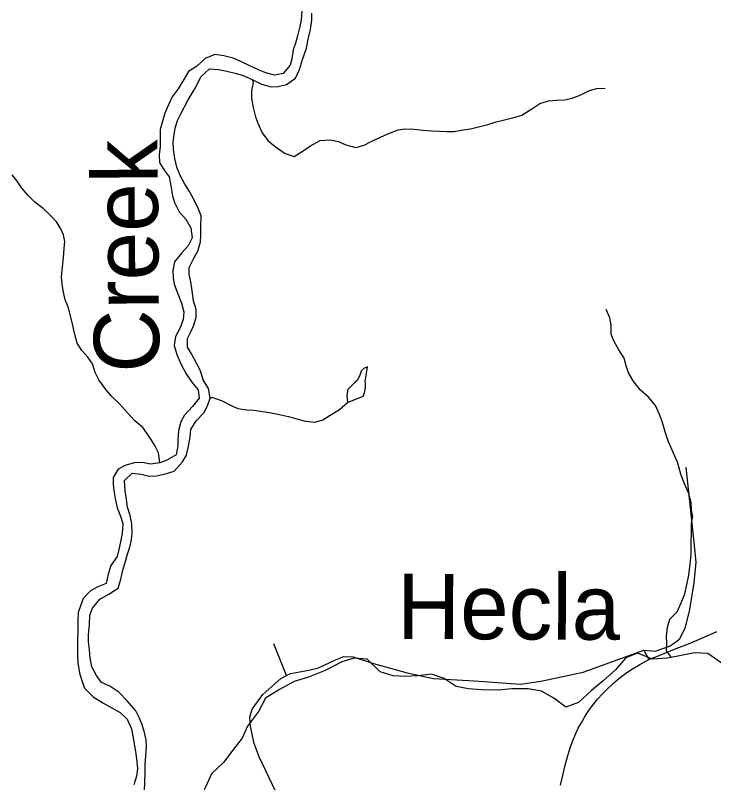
# Model space of a CAD drawing. Extents: x 0 to 34, y 0 to 22.
# Drawn here: x 3.746 to 4.76, y 17.398 to 18.512 of the extents above; entities that cross this region are included whole.
import ezdxf

# ---------------------------------------------------------------- set-up
doc = ezdxf.new("R2010")
doc.units = 0
for name, color, linetype in [('GM_X_County_Road', 7, 'Continuous'), ('GM_X_Major_River', 7, 'Continuous'), ('GM_X_Minor_Lake', 7, 'Continuous'), ('GM_X_Minor_River', 7, 'Continuous'), ('GM_X_Minor_River_Text', 7, 'Continuous'), ('GM_X_State_Route', 7, 'Continuous'), ('GM_X_Township_Road', 7, 'Continuous')]:
    doc.layers.add(name, color=color, linetype=linetype)

msp = doc.modelspace()

# ---------------------------------------------------------------- linework, layer by layer
at = {"layer": 'GM_X_County_Road'}
msp.add_lwpolyline([(4.1244, 17.385), (4.1095, 17.4154), (4.1001, 17.4361), (4.093, 17.4552), (4.0874, 17.48), (4.0866, 17.4937), (4.0899, 17.5051), (4.1055, 17.5264), (4.1314, 17.5498), (4.1395, 17.554), (4.1456, 17.5571), (4.1722, 17.5618), (4.1859, 17.565), (4.2108, 17.5766), (4.2227, 17.5817), (4.2363, 17.581), (4.266, 17.5716), (4.3146, 17.5577), (4.3531, 17.5497), (4.4121, 17.5461), (4.4791, 17.5413), (4.5087, 17.5456), (4.57, 17.5588), (4.6581, 17.5909), (4.6656, 17.5771)], dxfattribs=at)
at = {"layer": 'GM_X_Major_River'}
for points in [[(4.1618, 18.5181), (4.1611, 18.5056), (4.1592, 18.4957), (4.1558, 18.4821), (4.1527, 18.4718), (4.1493, 18.462), (4.1474, 18.449), (4.1448, 18.4396), (4.135, 18.4278), (4.1225, 18.4251), (4.1096, 18.4285), (4.0998, 18.4323), (4.0873, 18.438), (4.0745, 18.4445), (4.0624, 18.4498), (4.0488, 18.4532), (4.0356, 18.4551), (4.0219, 18.4493), (4.0095, 18.438), (3.9974, 18.4307), (3.9906, 18.419), (3.9826, 18.4053), (3.9739, 18.3935), (3.9686, 18.3821), (3.9633, 18.37), (3.9599, 18.3586), (3.9562, 18.3461), (3.9565, 18.3324), (3.9565, 18.3218), (3.955, 18.3096), (3.9554, 18.2982), (3.9622, 18.2872), (3.9694, 18.2774), (3.972, 18.2645), (3.9743, 18.25), (3.9773, 18.2402), (3.9841, 18.2269), (3.9936, 18.2163), (4.0007, 18.2034), (4.003, 18.1893), (3.9969, 18.1775), (3.9871, 18.1669), (3.9773, 18.1544), (3.9746, 18.1415), (3.9754, 18.1312), (3.9769, 18.1217), (3.9822, 18.1077), (3.9871, 18.0944), (3.9909, 18.0819), (3.9897, 18.0705), (3.9852, 18.0587), (3.9784, 18.0458), (3.9765, 18.0329), (3.9807, 18.0196), (3.9867, 18.0052), (3.9939, 17.9919), (4.0022, 17.9798), (4.0113, 17.9684), (4.0128, 17.9562), (4.0033, 17.9441), (3.9916, 17.9319), (3.9863, 17.922), (3.9829, 17.9091), (3.9818, 17.8966), (3.9818, 17.8871), (3.9795, 17.8742), (3.9659, 17.8666), (3.9561, 17.8624), (3.9425, 17.8605), (3.9307, 17.8632), (3.9186, 17.8628), (3.9054, 17.8586), (3.8956, 17.8533), (3.8884, 17.8415), (3.8884, 17.8316), (3.8892, 17.8222), (3.891, 17.8108), (3.8941, 17.7975)], [(3.9148, 17.7508), (3.9156, 17.7603), (3.9152, 17.7743), (3.913, 17.7861), (3.9092, 17.7982), (3.9073, 17.8093), (3.9054, 17.8218), (3.9047, 17.837), (3.9156, 17.8476), (3.9288, 17.8461), (3.9406, 17.8431), (3.9512, 17.8438), (3.964, 17.8465), (3.9769, 17.8507), (3.9886, 17.864), (3.9946, 17.8735), (3.9977, 17.8867), (3.9999, 17.9), (4.0011, 17.911), (4.0086, 17.9236), (4.02, 17.9354), (4.0256, 17.9467), (4.029, 17.9566), (4.0264, 17.9707), (4.0188, 17.9832), (4.0151, 17.9961), (4.0094, 18.0063), (4.0018, 18.0208), (3.9962, 18.0306), (3.9958, 18.0432), (4.0011, 18.0527), (4.0052, 18.0625), (4.0086, 18.0739), (4.0086, 18.0849), (4.0049, 18.0975), (4.0026, 18.1123), (4.0011, 18.1252), (3.9985, 18.1365), (3.9985, 18.146), (4.0053, 18.1597), (4.0109, 18.1696), (4.0151, 18.1833), (4.0155, 18.1935), (4.0155, 18.2057), (4.0159, 18.2208), (4.0121, 18.2307), (4.0057, 18.244), (3.9988, 18.2565), (3.992, 18.2668), (3.9852, 18.2797), (3.9807, 18.2918), (3.9777, 18.3043), (3.9758, 18.3176), (3.975, 18.3279), (3.9766, 18.3389), (3.9781, 18.3484), (3.9815, 18.3594), (3.9864, 18.3689), (3.9977, 18.3901), (4.0083, 18.4076), (4.0155, 18.4228), (4.028, 18.4342), (4.0408, 18.4334), (4.0533, 18.4308), (4.065, 18.4281), (4.0767, 18.4247), (4.09, 18.419), (4.1036, 18.4122), (4.1172, 18.408), (4.1274, 18.4088), (4.1399, 18.4115), (4.1527, 18.421), (4.1584, 18.4335), (4.1629, 18.4479), (4.1686, 18.4642), (4.1713, 18.4775), (4.1743, 18.4912), (4.1766, 18.5052), (4.1766, 18.5151)], [(3.8941, 17.7975), (3.899, 17.7853), (3.902, 17.7747), (3.9012, 17.7599), (3.899, 17.7481), (3.8963, 17.7367), (3.8941, 17.7269), (3.885, 17.7136), (3.8808, 17.701), (3.8782, 17.6874), (3.8657, 17.6824), (3.8551, 17.6767), (3.8445, 17.6657), (3.8407, 17.6551), (3.8373, 17.6452), (3.837, 17.6323), (3.837, 17.6187), (3.8362, 17.6054), (3.8362, 17.5932), (3.8362, 17.583), (3.8369, 17.5727), (3.8392, 17.5575), (3.8426, 17.5469), (3.8464, 17.5355), (3.8592, 17.523), (3.8732, 17.5143), (3.8861, 17.5071), (3.8982, 17.5002), (3.9084, 17.4904), (3.9148, 17.4767), (3.9167, 17.4661), (3.919, 17.4521), (3.9212, 17.441), (3.9227, 17.4289), (3.9235, 17.4183), (3.922, 17.408), (3.9182, 17.3955)], [(3.9337, 17.3872), (3.9341, 17.3985), (3.9345, 17.4126), (3.9348, 17.4247), (3.9356, 17.4373), (3.9363, 17.4502), (3.936, 17.4608), (3.9333, 17.4733), (3.9299, 17.4836), (3.9261, 17.4931), (3.9209, 17.5029), (3.9084, 17.5173), (3.8963, 17.5299), (3.8834, 17.5386), (3.871, 17.5439), (3.8638, 17.5541), (3.8574, 17.5667), (3.8547, 17.5796), (3.8536, 17.591), (3.8525, 17.6027), (3.8525, 17.6126), (3.8536, 17.6274), (3.8543, 17.6414), (3.8581, 17.6517), (3.8687, 17.6646), (3.8819, 17.6722), (3.8956, 17.6806), (3.8993, 17.6938), (3.902, 17.7068), (3.9054, 17.7181), (3.9092, 17.7299), (3.9122, 17.7402), (3.9148, 17.7508)]]:
    msp.add_lwpolyline(points, dxfattribs=at)
at = {"layer": 'GM_X_Minor_Lake'}
for points in [[(4.257, 18.002), (4.2521, 17.9994), (4.2479, 17.9956), (4.2456, 17.9884), (4.2422, 17.9819), (4.2388, 17.9793), (4.2289, 17.9691), (4.2274, 17.9607), (4.2282, 17.9499)], [(4.2282, 17.9499), (4.2508, 17.9595), (4.2527, 17.9641), (4.2543, 17.972), (4.2543, 17.9777), (4.2539, 17.9804), (4.257, 18.002)]]:
    msp.add_lwpolyline(points, dxfattribs=at)
at = {"layer": 'GM_X_Minor_River'}
for points in [[(4.09, 18.419), (4.0911, 18.4149), (4.0888, 18.4019), (4.0888, 18.3913), (4.0911, 18.3784), (4.0949, 18.3647), (4.0983, 18.3553), (4.1043, 18.3416), (4.1126, 18.3302), (4.1232, 18.3215), (4.1376, 18.3116), (4.1508, 18.3071), (4.164, 18.3154), (4.1743, 18.3227), (4.1886, 18.3303), (4.203, 18.3314), (4.2151, 18.3291), (4.2257, 18.3242), (4.2404, 18.3204), (4.2525, 18.3235), (4.2627, 18.3288), (4.2763, 18.3352), (4.2869, 18.3402), (4.3016, 18.3459), (4.3115, 18.3474), (4.3251, 18.347), (4.3379, 18.3452), (4.3504, 18.3444), (4.3617, 18.3437), (4.3723, 18.3433), (4.3829, 18.3433), (4.3961, 18.3456), (4.4067, 18.3475), (4.4203, 18.3509), (4.4305, 18.3532), (4.4438, 18.3574), (4.4559, 18.3604), (4.4695, 18.3635), (4.4812, 18.3669), (4.4956, 18.3764), (4.5073, 18.384), (4.5201, 18.3878), (4.5319, 18.3889), (4.5432, 18.3893), (4.5542, 18.3916), (4.567, 18.3965), (4.5795, 18.403), (4.5901, 18.4057), (4.6022, 18.4064)], [(3.9561, 17.8624), (3.9538, 17.8772), (3.9485, 17.8875), (3.9402, 17.9008), (3.9311, 17.9137), (3.9194, 17.9235), (3.9088, 17.9353), (3.8975, 17.9482), (3.8862, 17.9588), (3.8775, 17.9691), (3.8673, 17.9831), (3.862, 17.9937), (3.8582, 18.0063), (3.8514, 18.0161), (3.8427, 18.0256), (3.8359, 18.0362), (3.8321, 18.0507), (3.8298, 18.0617), (3.8234, 18.0875), (3.8185, 18.0992), (3.8155, 18.1121), (3.814, 18.1224), (3.8132, 18.1326), (3.8163, 18.1607), (3.817, 18.1736), (3.8182, 18.1839), (3.8159, 18.1934), (3.8117, 18.2029), (3.8057, 18.2124), (3.7962, 18.2226), (3.7864, 18.2317), (3.7747, 18.2408), (3.7649, 18.2507), (3.7558, 18.2613), (3.749, 18.2712), (3.7414, 18.2806)], [(4.6984, 17.5801), (4.6912, 17.5896), (4.6916, 17.6006), (4.6909, 17.6105), (4.6928, 17.6242), (4.6958, 17.6355), (4.7068, 17.6465), (4.7122, 17.6594), (4.7179, 17.6723), (4.7213, 17.6878), (4.7236, 17.6996), (4.7256, 17.7155), (4.7271, 17.73), (4.7271, 17.7459), (4.7276, 17.7622), (4.7276, 17.7752), (4.7291, 17.7846), (4.7276, 17.7941), (4.7269, 17.8051), (4.7228, 17.8192), (4.7171, 17.8321), (4.7119, 17.8462), (4.707, 17.8637), (4.6942, 17.893), (4.6893, 17.9074), (4.6848, 17.9226), (4.6811, 17.9329), (4.675, 17.9458), (4.6649, 17.958), (4.6531, 17.9683), (4.6437, 17.9801), (4.6358, 17.9931), (4.6328, 18.0033), (4.6298, 18.0143), (4.6219, 18.0265), (4.6147, 18.0398), (4.611, 18.0493), (4.6106, 18.0622), (4.6087, 18.0729), (4.6035, 18.0851), (4.6035, 18.0839)], [(4.029, 17.9566), (4.0313, 17.9578), (4.0464, 17.9528), (4.0585, 17.9464), (4.0691, 17.9415), (4.0823, 17.9396), (4.0922, 17.9388), (4.1054, 17.9373), (4.1152, 17.9354), (4.1273, 17.9331), (4.1424, 17.9297), (4.1526, 17.9267), (4.167, 17.9229), (4.1806, 17.9214), (4.1923, 17.9252), (4.2029, 17.9317), (4.2165, 17.94), (4.2282, 17.9499)], [(4.774, 17.5698), (4.7509, 17.5858), (4.7316, 17.587), (4.71, 17.5824), (4.6926, 17.579), (4.6714, 17.5779), (4.6491, 17.5863), (4.632, 17.5798), (4.6172, 17.5623), (4.5994, 17.546), (4.5823, 17.5323), (4.5634, 17.5148), (4.5452, 17.508), (4.5274, 17.5209), (4.5096, 17.5312), (4.4903, 17.5347), (4.4669, 17.5347), (4.4472, 17.5328), (4.4226, 17.5332), (4.404, 17.5348), (4.3859, 17.5382), (4.3685, 17.5496), (4.3499, 17.5561), (4.3303, 17.5535), (4.3125, 17.5527), (4.2943, 17.5535), (4.2754, 17.5592), (4.2569, 17.5775), (4.2379, 17.5791), (4.2201, 17.5738), (4.1959, 17.5612), (4.1716, 17.5517), (4.1508, 17.5453), (4.1296, 17.5335), (4.1091, 17.521), (4.0992, 17.5016)], [(4.0992, 17.5016), (4.0829, 17.4803), (4.0753, 17.4632), (4.0612, 17.4453), (4.0487, 17.4282), (4.0309, 17.4114), (4.0225, 17.3928), (4.0122, 17.3715), (3.9967, 17.3494), (3.9822, 17.3266), (3.9667, 17.3057), (3.9575, 17.2875), (3.9401, 17.2783), (3.9261, 17.2609), (3.9067, 17.2464), (3.8885, 17.2415), (3.8689, 17.2427), (3.85, 17.2587), (3.8341, 17.2758), (3.8263, 17.2827)]]:
    msp.add_lwpolyline(points, dxfattribs=at)
at = {"layer": 'GM_X_State_Route'}
msp.add_lwpolyline([(4.5375, 17.3946), (4.5405, 17.4088), (4.5436, 17.4217), (4.5477, 17.4379), (4.5518, 17.4503), (4.5558, 17.4606), (4.5597, 17.47), (4.5629, 17.4775), (4.5672, 17.485), (4.5734, 17.4957), (4.5794, 17.5044), (4.5856, 17.5129), (4.5912, 17.5195), (4.5981, 17.5275), (4.6048, 17.5342), (4.614, 17.5426), (4.6216, 17.5491), (4.6318, 17.557), (4.6396, 17.5623), (4.6524, 17.5699), (4.6656, 17.5771), (4.6757, 17.5812), (4.6886, 17.5865), (4.7029, 17.5922), (4.7254, 17.601), (4.7457, 17.6094), (4.7641, 17.6178)], dxfattribs=at)
at = {"layer": 'GM_X_Township_Road'}
msp.add_line((4.1395, 17.554), (4.1212, 17.5998), dxfattribs=at)
for points in [[(4.7048, 17.6029), (4.7107, 17.6072), (4.7188, 17.6242), (4.725, 17.6497), (4.7313, 17.6884), (4.7342, 17.7184), (4.7306, 17.7519), (4.7195, 17.8561)], [(4.6581, 17.5909), (4.6746, 17.5892), (4.6955, 17.5963), (4.7014, 17.6005), (4.7048, 17.6029)]]:
    msp.add_lwpolyline(points, dxfattribs=at)

# ---------------------------------------------------------------- texts
at = {"layer": 'GM_X_Minor_River_Text'}
for s, height, rotation, p in [('Creek', 0.09478, 90.4942, (3.9553, 17.9939)), ('Hecla', 0.09469, 359.7563, (4.3001, 17.6071))]:
    msp.add_text(s, height=height, rotation=rotation, dxfattribs=at).set_placement(p)

doc.saveas('drawing.dxf')
